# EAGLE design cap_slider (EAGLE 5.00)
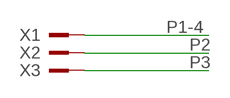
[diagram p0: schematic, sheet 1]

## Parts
X1  PIN  [PIN]
X2  PIN  [PIN]
X3  PIN  [PIN]

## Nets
P1-4: X1.P$1(KL)
P2: X2.P$1(KL)
P3: X3.P$1(KL)

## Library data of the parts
X1-X3 = xRemote:PIN

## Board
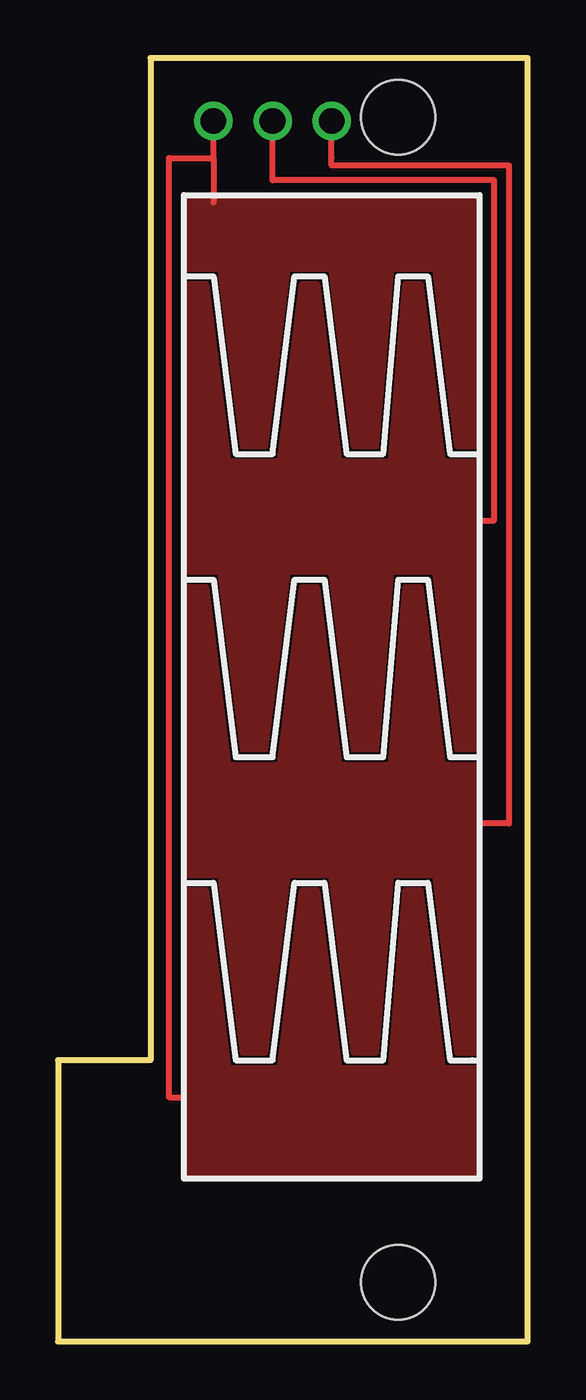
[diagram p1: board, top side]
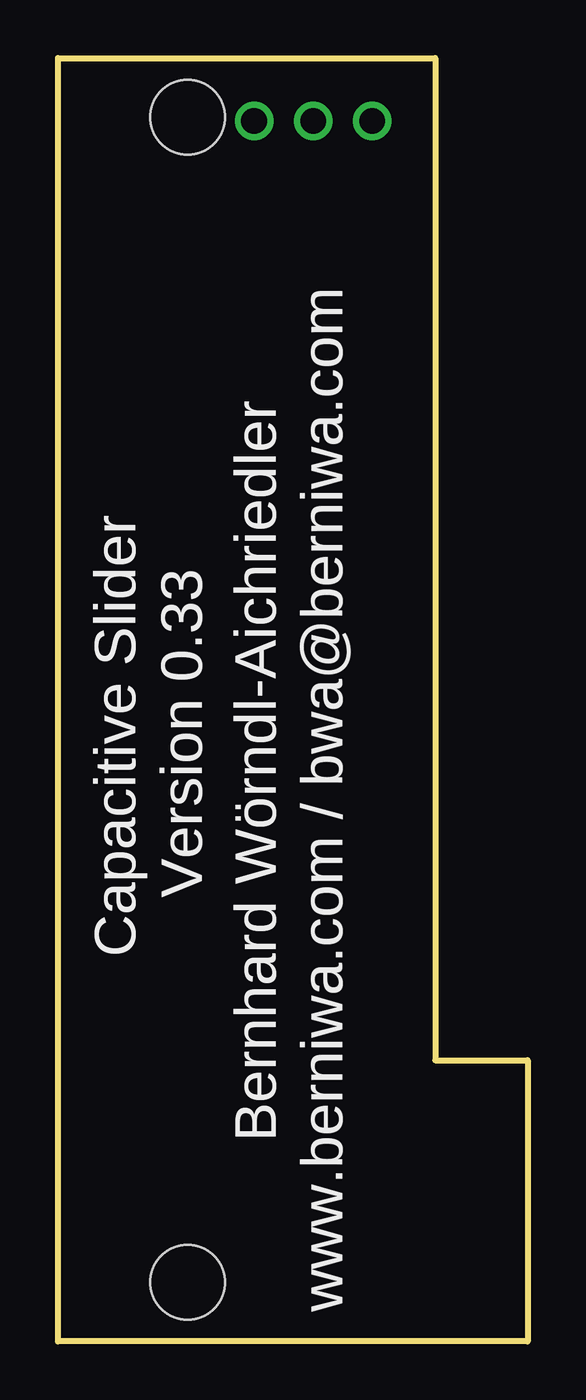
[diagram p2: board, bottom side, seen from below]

Size 20.16 x 55.09 mm. Coordinates in mm from the lower left corner, seen from the top.
Outline: 0,0 20.16,0 20.16,55.09 3.97,55.09 3.97,12.06 0,12.06 0,0
Copper layers (1*16): Top 0.035mm / dielectric 1.5mm / Bottom 0.035mm
Design rules "default": minimum track width 10mil, minimum drill 24mil, track to track 8mil, track to pad 8mil, pad to pad 8mil, via to via 8mil, smd to smd 8mil, copper to edge 40mil, drill to drill 8mil, minimum pad ring 10mil, minimum via ring 8mil, stop-mask expansion 4mil, vias tented up to drill 0mil, thermal gap 10mil
Holes 3.2 mm at 14.61,2.54 14.61,52.55

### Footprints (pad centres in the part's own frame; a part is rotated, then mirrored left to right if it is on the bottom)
PIN = drill 1.1 round: P$1 0,0

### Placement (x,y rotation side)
X1  6.67,52.39 0 top
X2  9.21,52.39 0 top
X3  11.75,52.39 0 top

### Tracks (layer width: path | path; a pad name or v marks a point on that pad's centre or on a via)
P1-4
  Top 0.254: 6.67,50.8 6.67,49.21 6.67,48.9 | 6.67,50.8 X1.P$1 | 6.67,50.8 4.76,50.8 4.76,10.48 5.4,10.48
  pour Top: 5.4,49.21 18.1,49.21 18.1,38.42 17.14,38.42 16.19,46.04 14.29,46.04 13.65,38.42 12.7,38.42 11.75,46.04 9.84,46.04 8.89,38.42 7.94,38.42 6.99,46.04 5.4,46.04
  pour Top: 5.4,19.37 6.35,19.37 7.3,11.75 9.53,11.75 10.48,19.37 11.11,19.37 12.06,11.75 14.29,11.75 14.92,19.37 15.56,19.37 16.51,11.75 18.1,11.75 18.1,6.99 5.4,6.99
P2
  Top 0.254: X2.P$1 9.21,49.85 18.73,49.85 18.73,35.24 18.1,35.24
  pour Top: 5.4,45.4 6.35,45.4 7.3,37.78 9.53,37.78 10.48,45.4 11.11,45.4 12.06,37.78 14.29,37.78 14.92,45.4 15.56,45.4 16.51,37.78 18.1,37.78 18.1,25.4 17.14,25.4 16.19,33.02 14.29,33.02 13.65,25.4 12.7,25.4 11.75,33.02 9.84,33.02 8.89,25.4 7.94,25.4 6.99,33.02 5.4,33.02
P3
  Top 0.254: X3.P$1 11.75,50.8 11.75,50.48 19.37,50.48 19.37,22.23 18.1,22.23
  pour Top: 5.4,32.38 6.35,32.38 7.3,24.77 9.53,24.77 10.48,32.38 11.11,32.38 12.06,24.77 14.29,24.77 14.92,32.38 15.56,32.38 16.51,24.77 18.1,24.77 18.1,12.38 17.14,12.38 16.19,20 14.29,20 13.65,12.38 12.7,12.38 11.75,20 9.84,20 8.89,12.38 7.94,12.38 6.99,20 5.4,20

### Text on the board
bPlace: Version 0.33 | Capacitive Slider | Bernhard Wörndl-Aichriedler | www.berniwa.com / bwa@berniwa.com
_bsilk: Version 0.33 | Capacitive Slider | Bernhard Wörndl-Aichriedler | www.berniwa.com / bwa@berniwa.com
